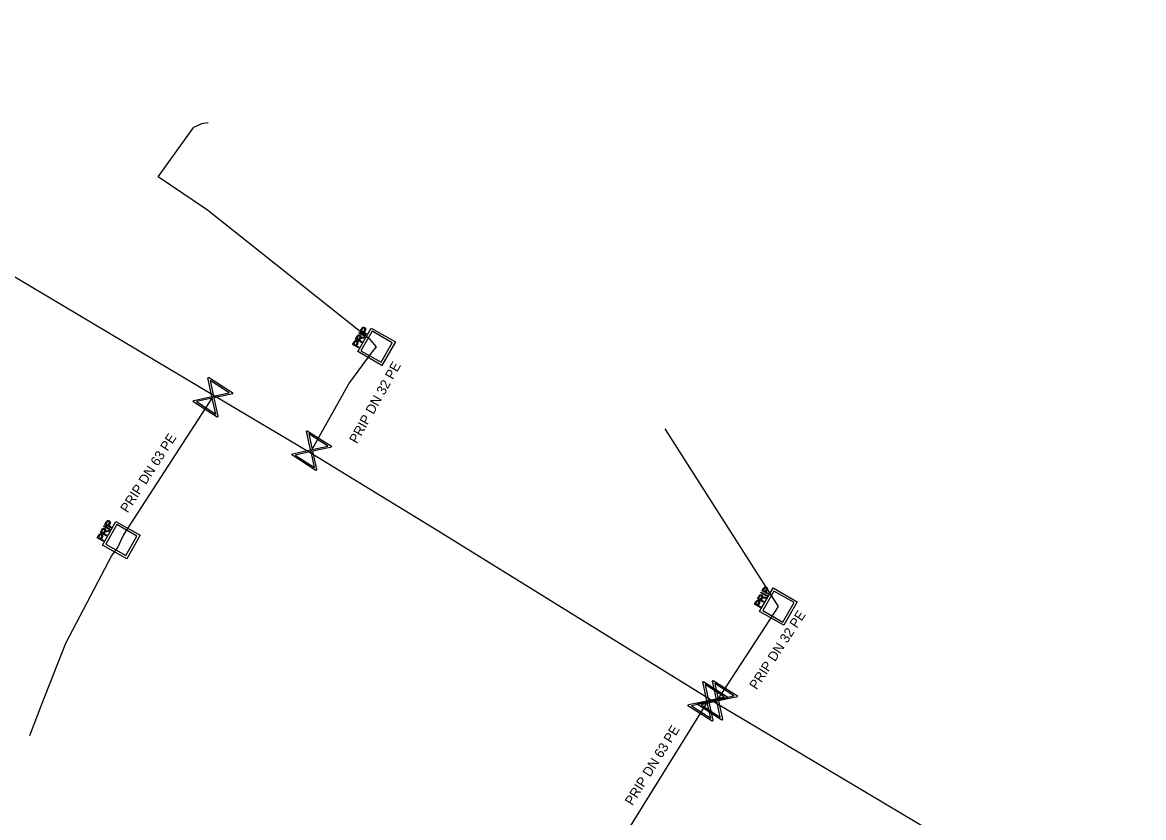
# Model space of a CAD drawing. Extents: x -643544 to -637295, y -1119190 to -1111715.
# Drawn here: x -642085.7 to -642027.3, y -1113629.4 to -1113588 of the extents above; entities that cross this region are included whole.
import ezdxf

# ---------------------------------------------------------------- set-up
doc = ezdxf.new("R2010")
doc.units = 0
for name, color, linetype in [('Default', 7, 'Continuous'), ('VP Popis přípojky', 7, 'Continuous'), ('VP Přípojka', 7, 'Continuous'), ('VP Řad', 7, 'Continuous'), ('VP Šachta', 7, 'Continuous'), ('VP Šoupě', 7, 'Continuous')]:
    doc.layers.add(name, color=color, linetype=linetype)

msp = doc.modelspace()

# ---------------------------------------------------------------- linework, layer by layer
at = {"layer": 'Default'}
for points in [[(-642068.043, -1113603.936), (-642068.026, -1113603.905), (-642068.013, -1113603.89), (-642067.996, -1113603.87), (-642067.976, -1113603.86), (-642067.957, -1113603.85), (-642067.932, -1113603.852), (-642067.908, -1113603.854), (-642067.885, -1113603.867), (-642067.845, -1113603.89), (-642067.832, -1113603.931), (-642067.819, -1113603.971), (-642067.857, -1113604.037)], [(-642067.893, -1113604.016), (-642067.87, -1113603.976), (-642067.875, -1113603.951), (-642067.88, -1113603.926), (-642067.908, -1113603.91), (-642067.927, -1113603.899), (-642067.946, -1113603.901), (-642067.965, -1113603.903), (-642067.979, -1113603.916), (-642067.988, -1113603.925), (-642068.004, -1113603.954)], [(-642068.272, -1113604.332), (-642068.248, -1113604.291), (-642068.227, -1113604.274), (-642068.206, -1113604.257), (-642068.178, -1113604.257), (-642068.149, -1113604.256), (-642068.124, -1113604.271), (-642068.09, -1113604.29), (-642068.08, -1113604.324), (-642068.07, -1113604.358), (-642068.089, -1113604.406), (-642068.071, -1113604.395), (-642068.059, -1113604.391), (-642068.033, -1113604.382), (-642067.998, -1113604.38)], [(-642068.139, -1113604.42), (-642068.122, -1113604.391), (-642068.119, -1113604.372), (-642068.116, -1113604.353), (-642068.124, -1113604.337), (-642068.132, -1113604.322), (-642068.148, -1113604.313), (-642068.169, -1113604.301), (-642068.193, -1113604.309), (-642068.216, -1113604.316), (-642068.236, -1113604.351)], [(-642068, -1113604.43), (-642068.039, -1113604.432), (-642068.06, -1113604.435), (-642068.082, -1113604.438), (-642068.093, -1113604.444), (-642068.104, -1113604.451), (-642068.112, -1113604.459), (-642068.118, -1113604.464), (-642068.127, -1113604.48)], [(-642068.442, -1113604.631), (-642068.425, -1113604.601), (-642068.412, -1113604.585), (-642068.395, -1113604.566), (-642068.375, -1113604.556), (-642068.356, -1113604.546), (-642068.331, -1113604.548), (-642068.307, -1113604.55), (-642068.284, -1113604.563), (-642068.244, -1113604.586), (-642068.231, -1113604.626), (-642068.218, -1113604.667), (-642068.256, -1113604.732)], [(-642068.292, -1113604.712), (-642068.269, -1113604.672), (-642068.274, -1113604.647), (-642068.28, -1113604.622), (-642068.307, -1113604.606), (-642068.326, -1113604.595), (-642068.345, -1113604.597), (-642068.365, -1113604.598), (-642068.378, -1113604.612), (-642068.387, -1113604.621), (-642068.404, -1113604.649)], [(-642081.562, -1113614.402), (-642081.538, -1113614.361), (-642081.517, -1113614.344), (-642081.496, -1113614.327), (-642081.468, -1113614.327), (-642081.439, -1113614.326), (-642081.414, -1113614.341), (-642081.38, -1113614.36), (-642081.37, -1113614.394), (-642081.36, -1113614.428), (-642081.379, -1113614.476), (-642081.361, -1113614.465), (-642081.349, -1113614.461), (-642081.323, -1113614.452), (-642081.288, -1113614.45)], [(-642081.429, -1113614.49), (-642081.412, -1113614.461), (-642081.409, -1113614.442), (-642081.406, -1113614.423), (-642081.414, -1113614.407), (-642081.422, -1113614.392), (-642081.438, -1113614.383), (-642081.459, -1113614.371), (-642081.483, -1113614.379), (-642081.506, -1113614.386), (-642081.526, -1113614.421)], [(-642081.333, -1113614.006), (-642081.316, -1113613.975), (-642081.303, -1113613.96), (-642081.286, -1113613.94), (-642081.266, -1113613.93), (-642081.247, -1113613.92), (-642081.222, -1113613.922), (-642081.198, -1113613.924), (-642081.175, -1113613.937), (-642081.135, -1113613.96), (-642081.122, -1113614.001), (-642081.109, -1113614.041), (-642081.147, -1113614.107)], [(-642081.183, -1113614.086), (-642081.16, -1113614.046), (-642081.165, -1113614.021), (-642081.17, -1113613.996), (-642081.198, -1113613.98), (-642081.217, -1113613.969), (-642081.236, -1113613.971), (-642081.255, -1113613.973), (-642081.269, -1113613.986), (-642081.278, -1113613.995), (-642081.294, -1113614.024)], [(-642081.732, -1113614.701), (-642081.715, -1113614.671), (-642081.702, -1113614.655), (-642081.685, -1113614.636), (-642081.665, -1113614.626), (-642081.646, -1113614.616), (-642081.621, -1113614.618), (-642081.597, -1113614.62), (-642081.574, -1113614.633), (-642081.534, -1113614.656), (-642081.521, -1113614.696), (-642081.508, -1113614.737), (-642081.546, -1113614.802)], [(-642081.582, -1113614.782), (-642081.559, -1113614.742), (-642081.564, -1113614.717), (-642081.57, -1113614.692), (-642081.597, -1113614.676), (-642081.616, -1113614.665), (-642081.635, -1113614.667), (-642081.655, -1113614.668), (-642081.668, -1113614.682), (-642081.677, -1113614.691), (-642081.694, -1113614.719)], [(-642081.29, -1113614.5), (-642081.329, -1113614.502), (-642081.35, -1113614.505), (-642081.372, -1113614.508), (-642081.383, -1113614.514), (-642081.394, -1113614.521), (-642081.402, -1113614.529), (-642081.408, -1113614.534), (-642081.417, -1113614.55)], [(-642047.352, -1113617.862), (-642047.328, -1113617.821), (-642047.307, -1113617.804), (-642047.286, -1113617.787), (-642047.258, -1113617.787), (-642047.229, -1113617.786), (-642047.204, -1113617.801), (-642047.17, -1113617.82), (-642047.16, -1113617.854), (-642047.15, -1113617.888), (-642047.169, -1113617.936), (-642047.151, -1113617.925), (-642047.139, -1113617.921), (-642047.113, -1113617.912), (-642047.078, -1113617.91)], [(-642047.219, -1113617.95), (-642047.202, -1113617.921), (-642047.199, -1113617.902), (-642047.196, -1113617.883), (-642047.204, -1113617.867), (-642047.212, -1113617.852), (-642047.228, -1113617.843), (-642047.249, -1113617.831), (-642047.273, -1113617.839), (-642047.296, -1113617.846), (-642047.316, -1113617.881)], [(-642047.123, -1113617.466), (-642047.106, -1113617.435), (-642047.093, -1113617.42), (-642047.076, -1113617.4), (-642047.056, -1113617.39), (-642047.037, -1113617.38), (-642047.012, -1113617.382), (-642046.988, -1113617.384), (-642046.965, -1113617.397), (-642046.925, -1113617.42), (-642046.912, -1113617.461), (-642046.899, -1113617.501), (-642046.937, -1113617.567)], [(-642046.973, -1113617.546), (-642046.95, -1113617.506), (-642046.955, -1113617.481), (-642046.96, -1113617.456), (-642046.988, -1113617.44), (-642047.007, -1113617.429), (-642047.026, -1113617.431), (-642047.045, -1113617.433), (-642047.059, -1113617.446), (-642047.068, -1113617.455), (-642047.084, -1113617.484)], [(-642047.522, -1113618.161), (-642047.505, -1113618.131), (-642047.492, -1113618.115), (-642047.475, -1113618.096), (-642047.455, -1113618.086), (-642047.436, -1113618.076), (-642047.411, -1113618.078), (-642047.387, -1113618.08), (-642047.364, -1113618.093), (-642047.324, -1113618.116), (-642047.311, -1113618.156), (-642047.298, -1113618.197), (-642047.336, -1113618.262)], [(-642047.372, -1113618.242), (-642047.349, -1113618.202), (-642047.354, -1113618.177), (-642047.36, -1113618.152), (-642047.387, -1113618.136), (-642047.406, -1113618.125), (-642047.425, -1113618.127), (-642047.445, -1113618.128), (-642047.458, -1113618.142), (-642047.467, -1113618.151), (-642047.484, -1113618.179)], [(-642047.08, -1113617.96), (-642047.119, -1113617.962), (-642047.14, -1113617.965), (-642047.162, -1113617.968), (-642047.173, -1113617.974), (-642047.184, -1113617.981), (-642047.192, -1113617.989), (-642047.198, -1113617.994), (-642047.207, -1113618.01)]]:
    msp.add_open_spline(points, degree=3, dxfattribs=at)
at = {"layer": 'VP Přípojka'}
for points in [[(-642070.71, -1113610.4), (-642070.64, -1113610.28), (-642068.7, -1113606.81), (-642067.48, -1113605.16), (-642067.26, -1113604.87), (-642067.59, -1113604.5), (-642071.825, -1113601.13), (-642076.06, -1113597.76), (-642078.63, -1113596.02), (-642076.78, -1113593.44), (-642076.35, -1113593.24), (-642076.02, -1113593.19)], [(-642080.55, -1113614.94), (-642080.43, -1113614.69), (-642075.78, -1113607.5), (-642075.72, -1113607.42)], [(-642049.59, -1113623.43), (-642049.51, -1113623.28), (-642046.52, -1113618.7), (-642046.34, -1113618.4), (-642052.23, -1113609.14)], [(-642085.31, -1113625.11), (-642084.69, -1113623.49), (-642083.44, -1113620.3), (-642081.22, -1113616.07), (-642081.06, -1113615.78), (-642080.73, -1113615.33), (-642080.55, -1113614.94)], [(-642057.11, -1113640.24), (-642056.05, -1113635.15), (-642054.836, -1113631.136), (-642054.58, -1113630.71), (-642050.01, -1113623.34), (-642049.93, -1113623.22)]]:
    msp.add_lwpolyline(points, dxfattribs=at)
at = {"layer": 'VP Řad'}
msp.add_lwpolyline([(-641996.54, -1113655.48), (-642004.64, -1113650.84), (-642026.25, -1113637.52), (-642031.11, -1113634.43), (-642049.59, -1113623.43), (-642049.93, -1113623.22), (-642064.25, -1113614.35), (-642070.71, -1113610.4), (-642075.72, -1113607.42), (-642093.8, -1113596.67), (-642094.42, -1113596.3), (-642111.743, -1113586.063), (-642112.05, -1113585.88), (-642127.8, -1113576.52), (-642134.05, -1113572.66), (-642156.48, -1113559.22)], dxfattribs=at)
at = {"layer": 'VP Šachta'}
for points in [[(-642067.537, -1113603.898), (-642066.277, -1113604.618), (-642066.978, -1113605.845), (-642068.238, -1113605.125), (-642067.537, -1113603.898)], [(-642068.039, -1113604.648), (-642068.35, -1113604.47), (-642068.272, -1113604.332)], [(-642068.236, -1113604.351), (-642068.292, -1113604.449), (-642068.189, -1113604.508)], [(-642068.189, -1113604.508), (-642068.139, -1113604.42)], [(-642067.857, -1113604.333), (-642068.169, -1113604.155), (-642068.146, -1113604.115), (-642067.834, -1113604.293), (-642067.857, -1113604.333)], [(-642068.127, -1113604.48), (-642068.154, -1113604.528), (-642068.015, -1113604.607), (-642068.039, -1113604.648)], [(-642067.798, -1113604.23), (-642068.11, -1113604.052), (-642068.043, -1113603.936)], [(-642068.071, -1113605.081), (-642067.025, -1113605.679), (-642066.444, -1113604.662), (-642067.489, -1113604.064), (-642068.071, -1113605.081)], [(-642068.004, -1113603.954), (-642068.05, -1113604.033), (-642067.939, -1113604.097)], [(-642067.998, -1113604.38), (-642067.882, -1113604.375), (-642067.912, -1113604.427), (-642068, -1113604.43)], [(-642067.939, -1113604.097), (-642067.893, -1113604.016)], [(-642067.857, -1113604.037), (-642067.903, -1113604.117), (-642067.775, -1113604.19), (-642067.798, -1113604.23)], [(-642068.198, -1113604.926), (-642068.509, -1113604.748), (-642068.442, -1113604.631)], [(-642068.404, -1113604.649), (-642068.449, -1113604.729), (-642068.338, -1113604.792)], [(-642068.338, -1113604.792), (-642068.292, -1113604.712)], [(-642068.256, -1113604.732), (-642068.302, -1113604.813), (-642068.175, -1113604.886), (-642068.198, -1113604.926)], [(-642081.329, -1113614.718), (-642081.64, -1113614.54), (-642081.562, -1113614.402)], [(-642081.526, -1113614.421), (-642081.582, -1113614.519), (-642081.479, -1113614.578)], [(-642080.827, -1113613.968), (-642079.567, -1113614.688), (-642080.268, -1113615.915), (-642081.528, -1113615.195), (-642080.827, -1113613.968)], [(-642081.147, -1113614.403), (-642081.459, -1113614.225), (-642081.436, -1113614.185), (-642081.124, -1113614.363), (-642081.147, -1113614.403)], [(-642081.088, -1113614.3), (-642081.4, -1113614.122), (-642081.333, -1113614.006)], [(-642081.361, -1113615.151), (-642080.315, -1113615.749), (-642079.734, -1113614.732), (-642080.779, -1113614.134), (-642081.361, -1113615.151)], [(-642081.294, -1113614.024), (-642081.34, -1113614.103), (-642081.229, -1113614.167)], [(-642081.229, -1113614.167), (-642081.183, -1113614.086)], [(-642081.147, -1113614.107), (-642081.193, -1113614.187), (-642081.065, -1113614.26), (-642081.088, -1113614.3)], [(-642081.488, -1113614.996), (-642081.799, -1113614.818), (-642081.732, -1113614.701)], [(-642081.694, -1113614.719), (-642081.739, -1113614.799), (-642081.628, -1113614.862)], [(-642081.628, -1113614.862), (-642081.582, -1113614.782)], [(-642081.546, -1113614.802), (-642081.592, -1113614.883), (-642081.465, -1113614.956), (-642081.488, -1113614.996)], [(-642081.479, -1113614.578), (-642081.429, -1113614.49)], [(-642081.417, -1113614.55), (-642081.444, -1113614.598), (-642081.305, -1113614.677), (-642081.329, -1113614.718)], [(-642081.288, -1113614.45), (-642081.172, -1113614.445), (-642081.202, -1113614.497), (-642081.29, -1113614.5)], [(-642047.119, -1113618.178), (-642047.43, -1113618), (-642047.352, -1113617.862)], [(-642047.316, -1113617.881), (-642047.372, -1113617.979), (-642047.269, -1113618.038)], [(-642046.617, -1113617.428), (-642045.357, -1113618.148), (-642046.058, -1113619.375), (-642047.318, -1113618.655), (-642046.617, -1113617.428)], [(-642046.937, -1113617.863), (-642047.249, -1113617.685), (-642047.226, -1113617.645), (-642046.914, -1113617.823), (-642046.937, -1113617.863)], [(-642046.878, -1113617.76), (-642047.19, -1113617.582), (-642047.123, -1113617.466)], [(-642047.151, -1113618.611), (-642046.105, -1113619.209), (-642045.524, -1113618.192), (-642046.569, -1113617.594), (-642047.151, -1113618.611)], [(-642047.084, -1113617.484), (-642047.13, -1113617.563), (-642047.019, -1113617.627)], [(-642047.078, -1113617.91), (-642046.962, -1113617.905), (-642046.992, -1113617.957), (-642047.08, -1113617.96)], [(-642047.019, -1113617.627), (-642046.973, -1113617.546)], [(-642046.937, -1113617.567), (-642046.983, -1113617.647), (-642046.855, -1113617.72), (-642046.878, -1113617.76)], [(-642047.278, -1113618.456), (-642047.589, -1113618.278), (-642047.522, -1113618.161)], [(-642047.484, -1113618.179), (-642047.529, -1113618.259), (-642047.418, -1113618.322)], [(-642047.418, -1113618.322), (-642047.372, -1113618.242)], [(-642047.336, -1113618.262), (-642047.382, -1113618.343), (-642047.255, -1113618.416), (-642047.278, -1113618.456)], [(-642047.269, -1113618.038), (-642047.219, -1113617.95)], [(-642047.207, -1113618.01), (-642047.234, -1113618.058), (-642047.095, -1113618.137), (-642047.119, -1113618.178)]]:
    msp.add_lwpolyline(points, dxfattribs=at)
at = {"layer": 'VP Šoupě'}
for points in [[(-642076.004, -1113606.463), (-642074.743, -1113607.276), (-642074.779, -1113607.331), (-642074.905, -1113607.354), (-642075.726, -1113607.533), (-642075.52, -1113608.481), (-642075.556, -1113608.537), (-642076.817, -1113607.724), (-642076.781, -1113607.669), (-642075.831, -1113607.465), (-642076.01, -1113606.645), (-642076.04, -1113606.519), (-642076.004, -1113606.463)], [(-642075.923, -1113606.627), (-642075.745, -1113607.447), (-642074.927, -1113607.269), (-642075.923, -1113606.627)], [(-642075.633, -1113608.375), (-642075.812, -1113607.552), (-642076.634, -1113607.73), (-642075.633, -1113608.375)], [(-642070.864, -1113609.243), (-642069.603, -1113610.056), (-642069.639, -1113610.111), (-642069.765, -1113610.134), (-642070.586, -1113610.313), (-642070.38, -1113611.261), (-642070.416, -1113611.317), (-642071.677, -1113610.504), (-642071.641, -1113610.449), (-642070.691, -1113610.245), (-642070.87, -1113609.425), (-642070.9, -1113609.299), (-642070.864, -1113609.243)], [(-642070.783, -1113609.407), (-642070.605, -1113610.227), (-642069.787, -1113610.049), (-642070.783, -1113609.407)], [(-642070.493, -1113611.155), (-642070.672, -1113610.332), (-642071.494, -1113610.51), (-642070.493, -1113611.155)], [(-642050.234, -1113622.303), (-642048.973, -1113623.116), (-642049.009, -1113623.171), (-642049.135, -1113623.194), (-642049.956, -1113623.373), (-642049.75, -1113624.321), (-642049.786, -1113624.377), (-642051.047, -1113623.564), (-642051.011, -1113623.509), (-642050.061, -1113623.305), (-642050.24, -1113622.485), (-642050.27, -1113622.359), (-642050.234, -1113622.303)], [(-642049.734, -1113622.243), (-642048.473, -1113623.056), (-642048.509, -1113623.111), (-642048.635, -1113623.134), (-642049.456, -1113623.313), (-642049.25, -1113624.261), (-642049.286, -1113624.317), (-642050.547, -1113623.504), (-642050.511, -1113623.449), (-642049.561, -1113623.245), (-642049.74, -1113622.425), (-642049.77, -1113622.299), (-642049.734, -1113622.243)], [(-642050.153, -1113622.467), (-642049.975, -1113623.287), (-642049.157, -1113623.109), (-642050.153, -1113622.467)], [(-642049.653, -1113622.407), (-642049.475, -1113623.227), (-642048.657, -1113623.049), (-642049.653, -1113622.407)], [(-642049.863, -1113624.215), (-642050.042, -1113623.392), (-642050.864, -1113623.57), (-642049.863, -1113624.215)], [(-642049.363, -1113624.155), (-642049.542, -1113623.332), (-642050.364, -1113623.51), (-642049.363, -1113624.155)]]:
    msp.add_lwpolyline(points, dxfattribs=at)

# ---------------------------------------------------------------- texts
at = {"layer": 'VP Popis přípojky'}
for s, rotation, p in [('PRIP DN 32 PE', 60.79141, (-642068.278, -1113609.953)), ('PRIP DN 63 PE', 57.10798, (-642080.219, -1113613.556)), ('PRIP DN 32 PE', 56.86195, (-642047.469, -1113622.767)), ('PRIP DN 63 PE', 58.19772, (-642053.94, -1113628.796))]:
    msp.add_text(s, height=0.5, rotation=rotation, dxfattribs=at).set_placement(p)

doc.saveas('drawing.dxf')
